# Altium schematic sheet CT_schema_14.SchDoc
size 742 x 377 mm
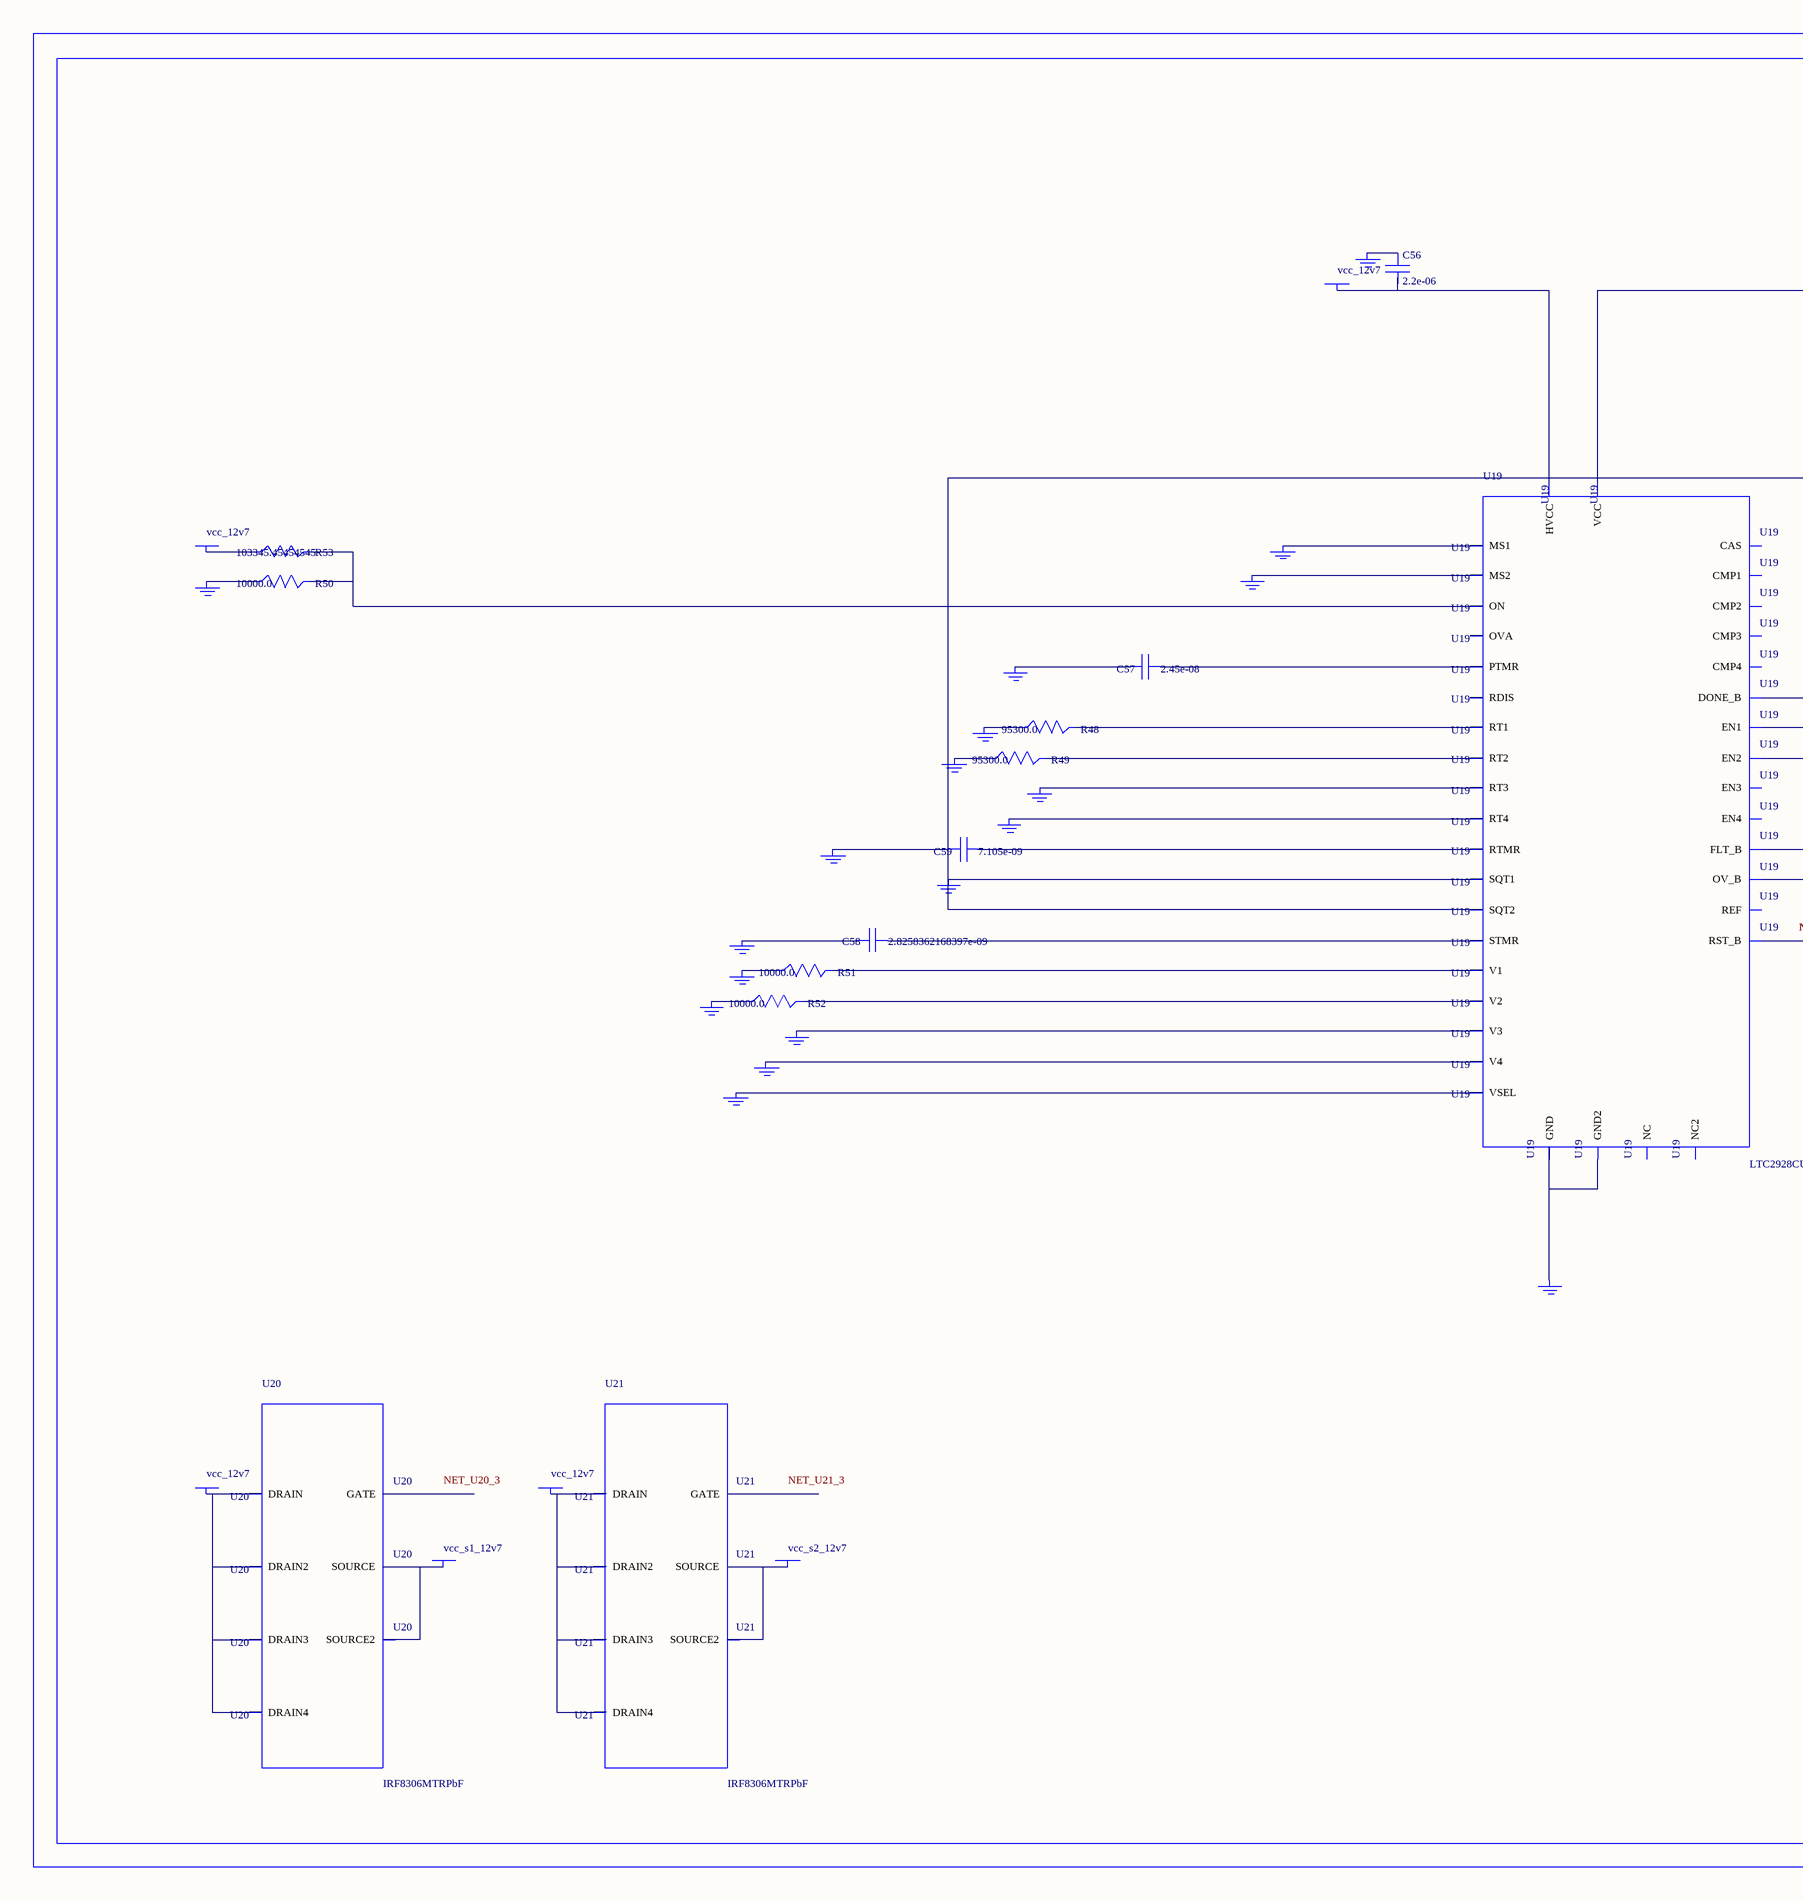
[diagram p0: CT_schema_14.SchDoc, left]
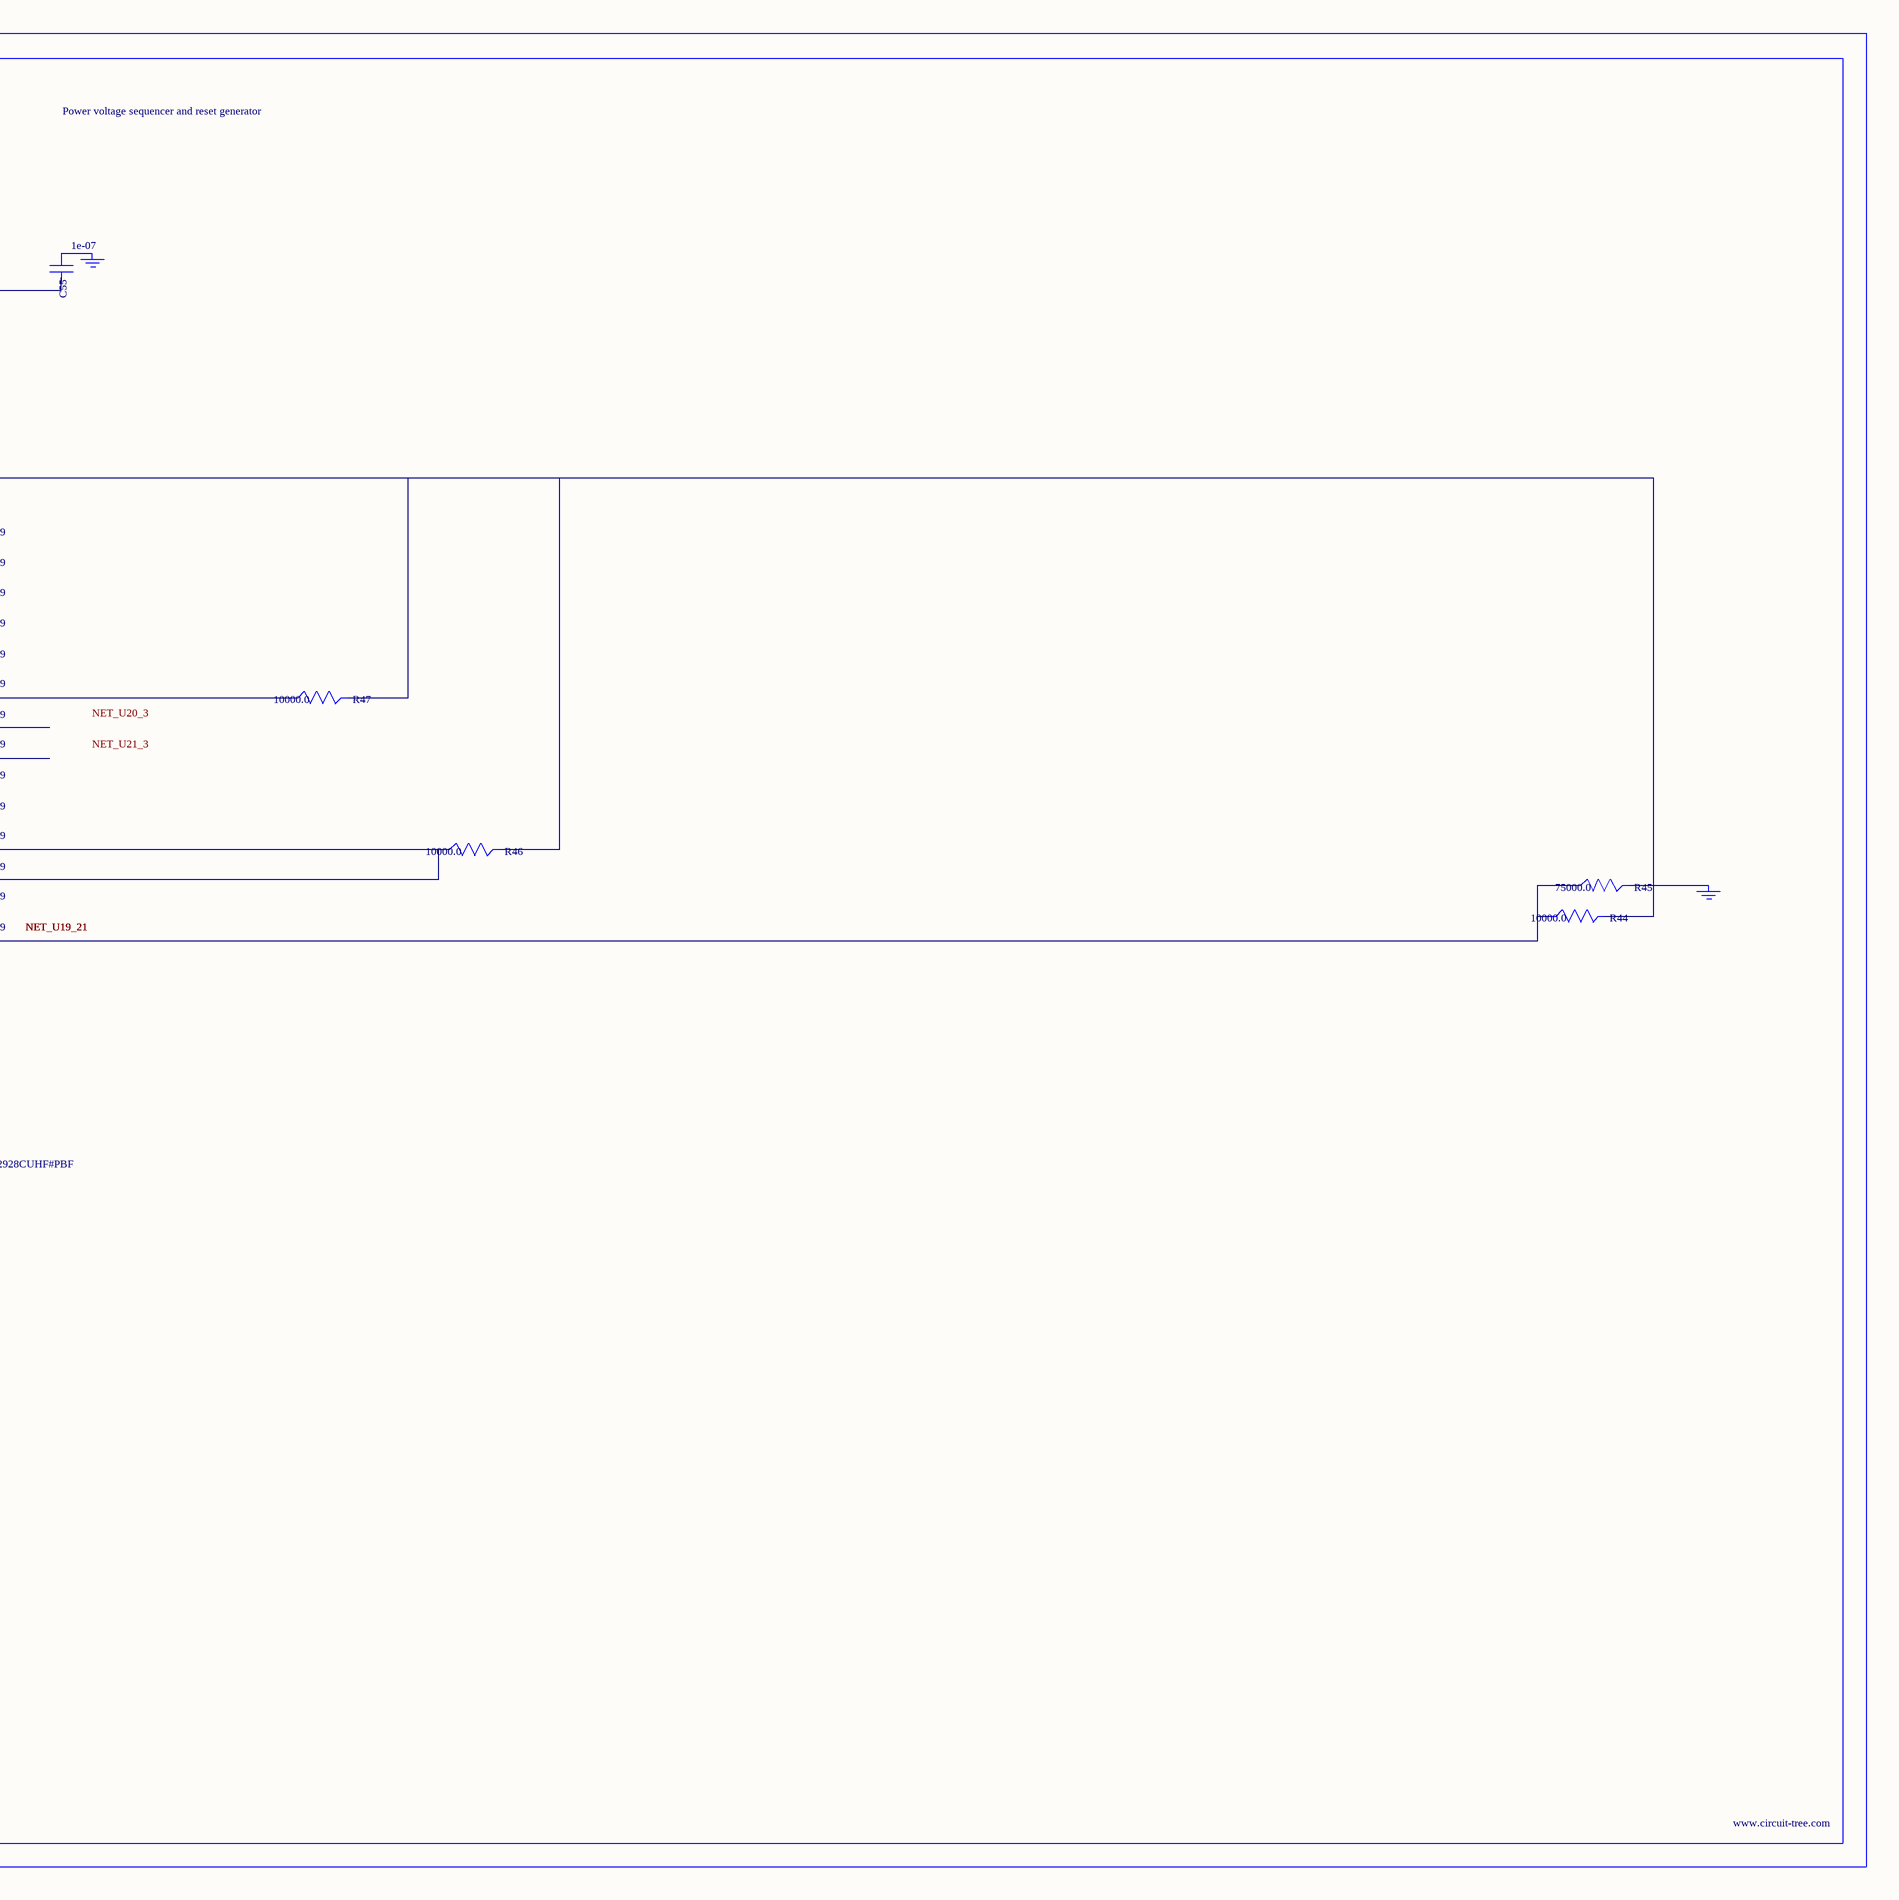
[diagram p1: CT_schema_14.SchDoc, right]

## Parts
BORDER13  (no value)
C55  1e-07  [C0402]
C56  2.2e-06  [C0603]
C57  2.45e-08  [R0603]
C58  2.8258362168397e-09  [R0603]
C59  7.105e-09  [R0603]
GND_INSTANCE_13_0  (no value)
GND_INSTANCE_13_1  (no value)
GND_INSTANCE_13_2  (no value)
GND_INSTANCE_13_3  (no value)
GND_INSTANCE_13_4  (no value)
GND_INSTANCE_13_5  (no value)
GND_INSTANCE_13_6  (no value)
GND_INSTANCE_13_7  (no value)
GND_INSTANCE_13_8  (no value)
GND_INSTANCE_13_9  (no value)
GND_INSTANCE_13_10  (no value)
GND_INSTANCE_13_11  (no value)
GND_INSTANCE_13_12  (no value)
GND_INSTANCE_13_13  (no value)
GND_INSTANCE_13_14  (no value)
GND_INSTANCE_13_15  (no value)
GND_INSTANCE_13_16  (no value)
GND_INSTANCE_13_17  (no value)
GND_INSTANCE_13_18  (no value)
GND_INSTANCE_13_19  (no value)
POWER_INSTANCE_13_0  vcc_12v7
POWER_INSTANCE_13_1  vcc_12v7
POWER_INSTANCE_13_2  vcc_12v7
POWER_INSTANCE_13_3  vcc_s1_12v7
POWER_INSTANCE_13_4  vcc_12v7
POWER_INSTANCE_13_5  vcc_s2_12v7
R44  10000.0  [R0603]
R45  75000.0  [R0603]
R46  10000.0  [R0603]
R47  10000.0  [R0603]
R48  95300.0  [R0603]
R49  95300.0  [R0603]
R50  10000.0  [R0603]
R51  10000.0  [R0603]
R52  10000.0  [R0603]
R53  103345.45454545  [R0603]
U19  LTC2928CUHF#PBF  [QFN-38_UHF]
U20  IRF8306MTRPbF  [IRF8306MTRPBF]
U21  IRF8306MTRPbF  [IRF8306MTRPBF]

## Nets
NetC55_1: C55.1 GND_INSTANCE_13_10.0(GND)
NetC55_2: C55.2 C59.2 GND_INSTANCE_13_5.0(GND) GND_INSTANCE_13_15.0(GND) R44.2 R46.2 R47.2 U19.10(SQT1) U19.11(SQT2) U19.22(VCC)
NetC56_1: C56.1 GND_INSTANCE_13_11.0(GND)
NetC56_2: C56.2 POWER_INSTANCE_13_1.0(PWR) U19.23(HVCC)
NetC57_1: C57.1 U19.27(PTMR)
NetC57_2: C57.2 GND_INSTANCE_13_14.0(GND)
NetC58_1: C58.1 U19.26(STMR)
NetC58_2: C58.2 GND_INSTANCE_13_13.0(GND)
NetC59_1: C59.1 U19.28(RTMR)
NetGND_INSTANCE_13_0_0: GND_INSTANCE_13_0.0(GND) R51.1
NetGND_INSTANCE_13_1_0: GND_INSTANCE_13_1.0(GND) R48.1
NetGND_INSTANCE_13_2_0: GND_INSTANCE_13_2.0(GND) R49.1
NetGND_INSTANCE_13_3_0: GND_INSTANCE_13_3.0(GND) U19.8(RT3)
NetGND_INSTANCE_13_4_0: GND_INSTANCE_13_4.0(GND) U19.9(RT4)
NetGND_INSTANCE_13_6_0: GND_INSTANCE_13_6.0(GND) U19.12(MS1)
NetGND_INSTANCE_13_7_0: GND_INSTANCE_13_7.0(GND) U19.13(MS2)
NetGND_INSTANCE_13_8_0: GND_INSTANCE_13_8.0(GND) R50.1
NetGND_INSTANCE_13_9_0: GND_INSTANCE_13_9.0(GND) R45.2
NetGND_INSTANCE_13_12_0: GND_INSTANCE_13_12.0(GND) U19.25(VSEL)
NetGND_INSTANCE_13_16_0: GND_INSTANCE_13_16.0(GND) U19.30(V4)
NetGND_INSTANCE_13_17_0: GND_INSTANCE_13_17.0(GND) U19.32(V3)
NetGND_INSTANCE_13_18_0: GND_INSTANCE_13_18.0(GND) R52.1
NetGND_INSTANCE_13_19_0: GND_INSTANCE_13_19.0(GND) U19.24(GND) U19.39(GND2)
NetPOWER_INSTANCE_13_0_0: POWER_INSTANCE_13_0.0(PWR) R53.1
NetPOWER_INSTANCE_13_2_0: POWER_INSTANCE_13_2.0(PWR) U20.1(DRAIN) U20.2(DRAIN2) U20.6(DRAIN3) U20.7(DRAIN4)
NetPOWER_INSTANCE_13_3_0: POWER_INSTANCE_13_3.0(PWR) U20.4(SOURCE) U20.5(SOURCE2)
NetPOWER_INSTANCE_13_4_0: POWER_INSTANCE_13_4.0(PWR) U21.1(DRAIN) U21.2(DRAIN2) U21.6(DRAIN3) U21.7(DRAIN4)
NetPOWER_INSTANCE_13_5_0: POWER_INSTANCE_13_5.0(PWR) U21.4(SOURCE) U21.5(SOURCE2)
NetR44_1: R44.1 R45.1 U19.21(RST_B)
NetR46_1: R46.1 U19.19(FLT_B) U19.20(OV_B)
NetR47_1: R47.1 U19.18(DONE_B)
NetR48_2: R48.2 U19.6(RT1)
NetR49_2: R49.2 U19.7(RT2)
NetR50_2: R50.2 R53.2 U19.16(ON)
NetR51_2: R51.2 U19.3(V1)
NetR52_2: R52.2 U19.38(V2)

Not connected (* = marked no-connect by the designer): U19 1(OVA) 2(EN1) 4(NC) 5(REF) 14(RDIS) 15(CAS) 17(NC2) 29(EN4) 31(EN3) 33(CMP3) 34(CMP4) 35(CMP1) 36(CMP2) 37(EN2); U20 3(GATE); U21 3(GATE)

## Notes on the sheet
- Labels drawn without touching a wire or pin: NET_U20_3, NET_U21_3

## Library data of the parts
BORDER13 = BORDER_PAGE13
C55 = C0402C104K3RACTU
C56 = GRM188R61H225KE1115D
C57 = C57
C58 = C58
C59 = C59
GND_INSTANCE_13_0-GND_INSTANCE_13_19 = GND
POWER_INSTANCE_13_0-POWER_INSTANCE_13_5 = PWR
R44 R46 R47 R50-R52 = RC0603JR-0710KL
R45 = RC0603JR-0775KL
R48 R49 = RC0603FR-0795K3L
R53 = R53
